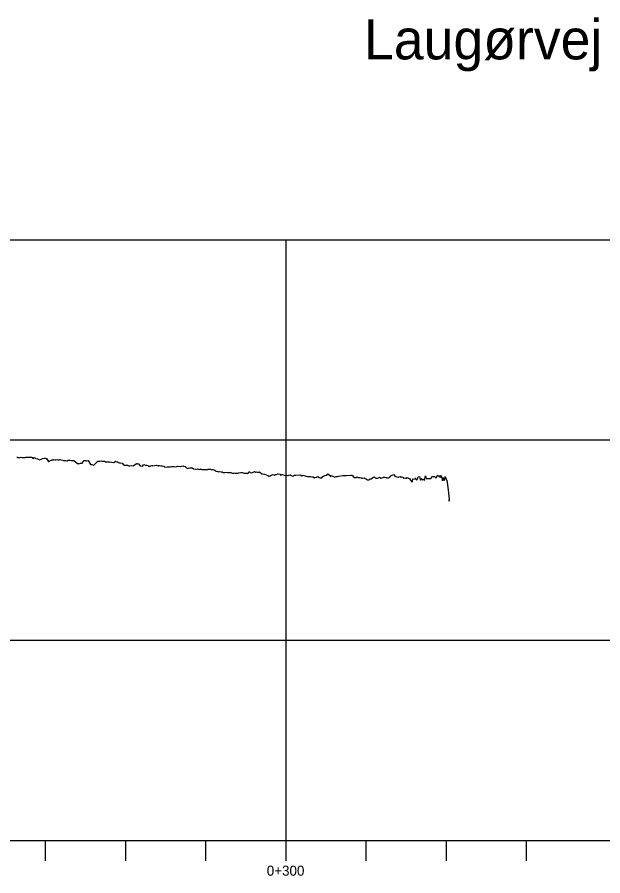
# Model space of a CAD drawing. Extents: x 0 to 513042, y 0 to 6212511.
# Drawn here: x 512366 to 512512.1, y 6211831.2 to 6212045.5 of the extents above; entities that cross this region are included whole.
import ezdxf

# ---------------------------------------------------------------- set-up
doc = ezdxf.new("R2010")
doc.units = 0
for name, color, linetype in [('TV_G_CL---', 7, 'Continuous'), ('TV_G_DTM_Exter', 7, 'Continuous'), ('TV_G_INF_SkrSg', 7, 'Continuous'), ('TV_L_INF_Title', 7, 'Continuous'), ('TV_L_VER_Punkt', 7, 'Continuous')]:
    doc.layers.add(name, color=color, linetype=linetype)

msp = doc.modelspace()

# ---------------------------------------------------------------- linework, layer by layer
at = {"layer": 'TV_G_CL---'}
msp.add_line((511933.07, 6211840.01), (513033.07, 6211840.01), dxfattribs=at)
at = {"layer": 'TV_G_DTM_Exter'}
for p, q in [((512373.07, 6211835.01), (512373.07, 6211840.01)), ((512393.07, 6211835.01), (512393.07, 6211840.01)), ((512413.07, 6211835.01), (512413.07, 6211840.01)), ((512433.07, 6211835.01), (512433.07, 6211840.01)), ((512453.07, 6211835.01), (512453.07, 6211840.01)), ((512473.07, 6211835.01), (512473.07, 6211840.01)), ((512493.07, 6211835.01), (512493.07, 6211840.01))]:
    msp.add_line(p, q, dxfattribs=at)
at = {"layer": 'TV_G_INF_SkrSg'}
msp.add_lwpolyline([(512365.91, 6211935.81), (512366.06, 6211935.64), (512366.33, 6211935.67), (512366.52, 6211935.57), (512366.97, 6211935.69), (512367.25, 6211935.64), (512367.54, 6211935.6), (512368.04, 6211935.64), (512368.18, 6211935.7), (512368.45, 6211935.74), (512368.56, 6211935.7), (512368.94, 6211935.69), (512369.16, 6211935.71), (512369.59, 6211935.73), (512369.77, 6211935.63), (512369.93, 6211935.43), (512370.23, 6211935.65), (512370.33, 6211935.54), (512370.38, 6211935.49), (512370.46, 6211935.52), (512370.65, 6211935.43), (512371.09, 6211935.35), (512371.59, 6211935.02), (512372.38, 6211935.42), (512372.92, 6211935.48), (512373.04, 6211935.53), (512373.17, 6211935.4), (512373.29, 6211935.36), (512373.78, 6211934.64), (512373.86, 6211934.64), (512374.07, 6211934.72), (512374.18, 6211934.77), (512374.7, 6211935.06), (512374.94, 6211935.07), (512375.07, 6211935.13), (512375.37, 6211935.09), (512375.67, 6211935.04), (512375.88, 6211935.13), (512376.17, 6211935.07), (512376.44, 6211935.1), (512376.57, 6211935.16), (512376.92, 6211935.07), (512377, 6211935.02), (512377.36, 6211934.94), (512377.68, 6211934.81), (512377.74, 6211934.83), (512377.86, 6211934.89), (512378.12, 6211934.91), (512378.46, 6211934.83), (512378.76, 6211934.96), (512378.94, 6211934.95), (512379.01, 6211934.98), (512379.17, 6211934.96), (512379.45, 6211934.91), (512379.65, 6211934.92), (512379.94, 6211934.89), (512380.08, 6211934.87), (512380.17, 6211934.91), (512381.04, 6211934.18), (512381.28, 6211934.13), (512381.4, 6211934.1), (512381.81, 6211934.2), (512381.91, 6211934.2), (512382.2, 6211934.21), (512382.71, 6211934.92), (512383.13, 6211934.86), (512383.21, 6211934.81), (512383.28, 6211934.84), (512383.7, 6211934.86), (512384.3, 6211933.91), (512384.6, 6211933.87), (512384.9, 6211933.78), (512385.13, 6211933.72), (512386.15, 6211934.7), (512386.61, 6211934.75), (512386.84, 6211934.77), (512387.09, 6211934.72), (512387.18, 6211934.76), (512387.55, 6211934.74), (512387.83, 6211934.71), (512387.98, 6211934.6), (512388.44, 6211934.55), (512388.81, 6211934.54), (512389.03, 6211934.46), (512389.13, 6211934.58), (512389.56, 6211934.45), (512390.14, 6211934.43), (512390.52, 6211934.69), (512390.62, 6211934.64), (512391.05, 6211934.56), (512391.25, 6211934.41), (512391.53, 6211934.29), (512391.66, 6211934.35), (512392.18, 6211934.22), (512392.54, 6211933.8), (512392.67, 6211933.75), (512392.89, 6211933.75), (512393, 6211933.75), (512393.18, 6211933.75), (512393.53, 6211933.7), (512393.81, 6211933.55), (512394.12, 6211933.6), (512394.44, 6211933.65), (512394.94, 6211933.52), (512395.77, 6211934.14), (512395.87, 6211934.1), (512395.99, 6211934.06), (512396.21, 6211934.16), (512396.68, 6211933.54), (512397.26, 6211933.44), (512397.56, 6211933.87), (512398.03, 6211933.73), (512398.36, 6211933.71), (512398.68, 6211933.67), (512398.79, 6211933.48), (512399.06, 6211933.51), (512399.13, 6211933.46), (512399.49, 6211933.62), (512399.61, 6211933.58), (512399.68, 6211933.62), (512399.75, 6211933.64), (512399.82, 6211933.6), (512400.26, 6211933.61), (512400.62, 6211933.69), (512400.67, 6211933.71), (512400.92, 6211933.64), (512401.16, 6211933.58), (512401.24, 6211933.62), (512401.32, 6211933.65), (512401.46, 6211933.63), (512401.83, 6211933.53), (512401.9, 6211933.56), (512402.15, 6211933.52), (512402.54, 6211933.44), (512402.81, 6211933.2), (512403.4, 6211933.28), (512403.54, 6211933.34), (512403.99, 6211933.3), (512404.2, 6211933.3), (512404.49, 6211933.43), (512404.77, 6211933.4), (512405.06, 6211933.37), (512405.51, 6211933.29), (512405.75, 6211933.39), (512405.84, 6211933.43), (512405.95, 6211933.48), (512406.17, 6211933.49), (512406.72, 6211933.39), (512406.81, 6211933.38), (512407.31, 6211933.59), (512407.5, 6211933.45), (512407.58, 6211933.48), (512407.91, 6211933.4), (512408.2, 6211933.06), (512408.41, 6211932.97), (512408.49, 6211932.91), (512408.73, 6211933.02), (512409.07, 6211933.08), (512409.27, 6211933.09), (512409.33, 6211933.04), (512409.68, 6211933.04), (512409.96, 6211932.79), (512410.04, 6211932.82), (512410.52, 6211932.76), (512410.62, 6211932.73), (512411, 6211932.82), (512411.22, 6211932.73), (512411.53, 6211932.68), (512411.64, 6211932.73), (512411.99, 6211932.73), (512412.08, 6211932.68), (512412.19, 6211932.63), (512412.68, 6211932.61), (512413.12, 6211932.62), (512413.23, 6211932.6), (512413.48, 6211932.61), (512413.66, 6211932.77), (512413.97, 6211932.72), (512414.2, 6211932.75), (512414.36, 6211932.63), (512414.51, 6211932.62), (512414.79, 6211932.65), (512415.19, 6211932.44), (512415.27, 6211932.47), (512415.35, 6211932.42), (512415.42, 6211932.36), (512415.61, 6211932.21), (512416.03, 6211932.12), (512416.27, 6211932.07), (512416.57, 6211932.11), (512416.89, 6211932.1), (512416.96, 6211932.05), (512417.12, 6211932.03), (512417.31, 6211931.92), (512417.7, 6211931.86), (512418.2, 6211931.99), (512418.56, 6211931.92), (512419.13, 6211931.89), (512419.2, 6211931.92), (512419.26, 6211931.87), (512419.44, 6211931.8), (512419.69, 6211931.76), (512420.05, 6211931.73), (512420.18, 6211931.79), (512420.33, 6211931.76), (512420.57, 6211931.71), (512420.63, 6211931.74), (512420.86, 6211931.75), (512421.11, 6211931.76), (512421.32, 6211931.78), (512421.8, 6211931.89), (512422.12, 6211931.88), (512422.37, 6211931.81), (512422.65, 6211931.71), (512422.96, 6211931.75), (512423.17, 6211931.75), (512423.38, 6211931.74), (512423.53, 6211931.66), (512423.7, 6211931.81), (512423.84, 6211932.18), (512424.12, 6211931.92), (512424.56, 6211931.83), (512424.85, 6211931.96), (512425.2, 6211932.11), (512425.42, 6211932.02), (512425.64, 6211932.04), (512425.96, 6211932), (512426.05, 6211931.96), (512426.22, 6211931.94), (512426.31, 6211931.98), (512426.42, 6211932.03), (512427.04, 6211931.54), (512427.16, 6211931.53), (512427.7, 6211931.46), (512428.1, 6211931.35), (512428.48, 6211931.14), (512428.76, 6211930.98), (512428.82, 6211931.01), (512429.15, 6211931.08), (512429.22, 6211931.11), (512429.81, 6211931.37), (512430.15, 6211931.22), (512430.4, 6211931.42), (512430.52, 6211931.4), (512430.57, 6211931.42), (512430.98, 6211931.6), (512431.11, 6211931.58), (512431.48, 6211931.44), (512431.77, 6211931.19), (512432.04, 6211931.5), (512432.38, 6211931.35), (512432.87, 6211931.19), (512433.08, 6211931.21), (512433.49, 6211931.11), (512433.55, 6211931.14), (512433.75, 6211931.22), (512434.05, 6211931.28), (512434.12, 6211931.31), (512434.33, 6211931.12), (512434.76, 6211931.02), (512434.96, 6211931.04), (512435.13, 6211931.21), (512435.46, 6211931.2), (512435.54, 6211931.23), (512436.61, 6211931.28), (512436.98, 6211931.08), (512437.21, 6211931.18), (512437.28, 6211931.22), (512437.79, 6211931.08), (512438.04, 6211931.02), (512438.4, 6211930.91), (512438.86, 6211930.87), (512439.07, 6211930.88), (512439.16, 6211930.87), (512439.5, 6211930.8), (512439.72, 6211930.81), (512440.14, 6211930.59), (512440.28, 6211930.66), (512440.67, 6211930.74), (512440.82, 6211930.8), (512440.96, 6211930.87), (512441.36, 6211930.64), (512441.56, 6211930.55), (512441.96, 6211930.55), (512442.23, 6211930.9), (512442.77, 6211931.14), (512443.11, 6211931.21), (512443.24, 6211931.26), (512443.47, 6211931.53), (512444.03, 6211931.16), (512444.08, 6211931.19), (512444.14, 6211930.8), (512444.38, 6211931.15), (512444.59, 6211931.07), (512445.16, 6211930.75), (512445.55, 6211930.92), (512445.71, 6211930.91), (512445.9, 6211930.9), (512446.17, 6211931.02), (512447.23, 6211931.16), (512447.65, 6211931.17), (512448.1, 6211931.11), (512448.17, 6211931.22), (512448.78, 6211931.16), (512449.23, 6211931.27), (512449.45, 6211931.21), (512449.61, 6211931.19), (512449.82, 6211930.94), (512450.15, 6211930.67), (512450.58, 6211930.69), (512450.64, 6211930.71), (512450.64, 6211930.72), (512450.71, 6211930.74), (512450.78, 6211930.78), (512451.05, 6211930.64), (512451.48, 6211930.66), (512451.83, 6211930.57), (512451.9, 6211930.51), (512452.1, 6211930.52), (512452.54, 6211930.54), (512452.78, 6211930.38), (512453.11, 6211930.2), (512453.41, 6211930.08), (512453.63, 6211930.09), (512453.77, 6211930.06), (512453.87, 6211930.17), (512454.02, 6211930.34), (512454.29, 6211930.29), (512454.69, 6211930.64), (512454.88, 6211930.73), (512455.03, 6211930.79), (512455.18, 6211930.68), (512455.31, 6211930.57), (512455.45, 6211930.46), (512455.87, 6211930.48), (512456.29, 6211930.66), (512456.35, 6211930.7), (512456.8, 6211930.46), (512457.29, 6211930.67), (512457.36, 6211930.7), (512457.68, 6211930.76), (512457.99, 6211930.65), (512458.18, 6211930.56), (512458.59, 6211930.57), (512458.92, 6211930.71), (512459.22, 6211931.1), (512459.54, 6211931.25), (512459.91, 6211931.41), (512460.17, 6211931), (512460.62, 6211930.78), (512460.96, 6211930.76), (512461.14, 6211930.75), (512461.2, 6211930.78), (512461.54, 6211930.93), (512461.79, 6211930.7), (512461.98, 6211930.79), (512462.26, 6211930.74), (512462.29, 6211930.68), (512462.38, 6211930.45), (512462.46, 6211930.49), (512462.69, 6211930.59), (512463.1, 6211930.43), (512463.3, 6211930.61), (512463.76, 6211930.38), (512463.81, 6211930.4), (512464.09, 6211930.02), (512464.5, 6211929.52), (512464.58, 6211929.64), (512464.68, 6211930.28), (512465.23, 6211930.26), (512465.32, 6211930.56), (512465.63, 6211930.1), (512465.83, 6211930.19), (512466.03, 6211930.79), (512466.31, 6211930.92), (512466.52, 6211930.07), (512466.63, 6211929.95), (512466.8, 6211930.36), (512466.88, 6211930.4), (512467.04, 6211929.96), (512467.28, 6211930.24), (512467.5, 6211929.99), (512467.58, 6211929.86), (512467.81, 6211931.07), (512468.04, 6211930.4), (512468.34, 6211930.44), (512468.53, 6211930.44), (512468.83, 6211930.4), (512469.19, 6211930.39), (512469.58, 6211930.91), (512469.65, 6211930.86), (512470.07, 6211930.88), (512470.41, 6211930.6), (512470.61, 6211930.68), (512470.83, 6211931.2), (512471.09, 6211931.06), (512471.41, 6211930.76), (512471.53, 6211931.16), (512471.57, 6211930.68), (512471.78, 6211931.11), (512472.06, 6211929.85), (512472.27, 6211930.63), (512472.46, 6211929.94), (512472.69, 6211930.38), (512472.74, 6211930.88), (512473.08, 6211930), (512473.16, 6211929.95), (512473.46, 6211927.53), (512473.58, 6211926.76), (512473.75, 6211925.28), (512473.77, 6211924.78), (512473.78, 6211925.19)], dxfattribs=at)
at = {"layer": 'TV_L_VER_Punkt'}
for p, q in [((511933.07, 6211990.01), (513033.07, 6211990.01)), ((511933.07, 6211990.01), (513033.07, 6211990.01)), ((512433.07, 6211840.01), (512433.07, 6211990.01)), ((511933.07, 6211940.01), (513033.07, 6211940.01)), ((511933.07, 6211890.01), (513033.07, 6211890.01))]:
    msp.add_line(p, q, dxfattribs=at)

# ---------------------------------------------------------------- texts
msp.add_text('0+300', height=2.5).set_placement((512428.25, 6211831.26))
at = {"layer": 'TV_L_INF_Title'}
msp.add_text('Laugørvej', height=10, dxfattribs=at).set_placement((512452.5, 6212035.01))

doc.saveas('drawing.dxf')
